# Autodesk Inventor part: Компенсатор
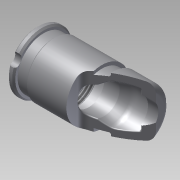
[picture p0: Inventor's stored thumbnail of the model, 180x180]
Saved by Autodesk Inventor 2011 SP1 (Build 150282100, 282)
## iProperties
Created: 2011-12
Part Number: Компенсатор
Document SubType Name: Modeling
Designer: EfimchenkoPA
Density: 1 g/cm^3
Author: EfimchenkoPA
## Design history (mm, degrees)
sketch "Эскиз1"
  geometry: L1 (0, 0)-(7.485, 0); L2 (0, 7.8)-(0, 9); L3 (0.5, 9.5)-(1.5, 9.5); L4 (2, 9)-(2, 8.25); L5 (2, 8.25)-(5, 8.25); L6 (5, 8.25)-(5.5, 8.75); L7 (5.5, 8.75)-(20.5, 8.75); L8 (20.5, 8.75)-(20.5, 7.75); L9 (20.5, 7.75)-(24.1, 7.75); L10 (24.1, 7.75)-(24.1, 8.75); L11 (24.1, 8.75)-(31.5, 8.75); L12 (33.5, 6.75)-(33.5, 5); L13 (33.5, 5)-(30.2, 5); L14 (30.2, 5)-(30.2, 6.5); L15 (30.2, 6.5)-(25.287, 6.5); L16 (23.596, 6.125)-(21.183, 5); L17 (21.183, 5)-(16.3, 5); L18 (16.3, 5)-(16.3, 7.05); L19 (16.3, 7.05)-(12.3, 7.05); L20 (12.3, 7.05)-(12.3, 7); L21 (12.3, 7)-(0.8, 7); L22 (0, 7.8)-(0.8, 7); L23 (0.5, 9.5)-(0, 9); L24 (1.5, 9.5)-(2, 9); A1 r 2 centre (31.5, 6.75) between (33.5, 6.75) and (31.5, 8.75); A2 r 4 centre (25.287, 2.5) between (25.287, 6.5) and (23.596, 6.125); 3 further points
  constraints: 48 end point, 14 parallel, 7 point on line, 4 perpendicular, 4 point on circle, 4 tangent, 2 centre point, 2 collinear, 1 horizontal
  dimensions: "d0" = 4 distance between parallel lines of L20 L18; "d1" = 7.05 distance between parallel lines of L19 L1; "d2" = 25 deg angle of L17 L16; "d3" = 5 distance between parallel lines of L17 L1; "d4" = 16.3 distance between parallel lines of L18 L2; "d5" = 7 distance between parallel lines of L1 L21; "d6" = 135 deg angle of L21 L22; "d7" = 0.8 horizontal distance of L2.start L21.end; "d8" = 8.25 distance between parallel lines of L1 L5; "d9" = 9.5 distance between parallel lines of L1 L3; "d10" = 2 distance between parallel lines of L2 L4; "d11" = 3 distance from line of L5.end L4; "d12" = 135 deg angle of L5 L6; "d13" = 8.75 distance between parallel lines of L7 L1; "d14" = 30.2 distance between parallel lines of L14 L2; "d15" = 5.8 distance from line of point (24.4, 6.5) L14; "d16" = 6.5 distance between parallel lines of L1 L15; "d17" = 2 radius of A1; "d18" = 33.5 distance between parallel lines of L12 L2; "d19" = 9.4 distance between parallel lines of L10 L12; "d20" = 3.6 distance between parallel lines of L8 L10; "d21" = 7.75 distance between parallel lines of L9 L1; "d22" = 4 radius of A2; "d23" = 0.5 distance of L3.start point (0, 9.5); "d24" = 0.5 distance of L2.end point (0, 9.5) (= d23); "d25" = 0.5 distance of L3.end point (2, 9.5) (= d23); "d26" = 0.5 distance of L4.start point (2, 9.5) (= d25)
revolve "Вращение1" sketch "Эскиз1" stored, may be unused: angle "d27" = 90 deg
sketch "Эскиз2"
  geometry: L1 (0, 9)-(0.5, 9.5) reference; L2 (0.5, 9.5)-(1.5, 9.5) reference; L3 (1.5, 9.5)-(2, 9) reference; L4 (2, 9)-(2, 8.25) reference; L5 (2, 8.25)-(5, 8.25) reference; L6 (5, 8.25)-(5.5, 8.75) reference; L7 (5.5, 8.75)-(20.5, 8.75) reference; L8 (20.5, 8.75)-(20.5, 7.75) reference; L9 (20.5, 7.75)-(24.1, 7.75) reference; L10 (24.1, 7.75)-(24.1, 8.75) reference; L11 (24.1, 8.75)-(31.5, 8.75) reference; L12 (33.5, 6.75)-(33.5, 5) reference; L13 (33.5, 5)-(30.2, 5) reference; L14 (30.2, 5)-(30.2, 6.5) reference; L15 (30.2, 6.5)-(25.287, 6.5) reference; L16 (23.596, 6.125)-(21.183, 5) reference; L17 (21.183, 5)-(16.3, 5) reference; L18 (16.3, 5)-(16.3, 7.05) reference; L19 (16.3, 7.05)-(12.3, 7.05) reference; L20 (12.3, 7.05)-(12.3, 7) reference; L21 (12.3, 7)-(0.8, 7) reference; L22 (0.8, 7)-(0, 7.8) reference; L23 (0, 7.8)-(0, 9) reference; L24 (0.5, -9.5)-(0, -9) reference; L25 (0, -9)-(0, -7.8) reference; L26 (0, -7.8)-(0.8, -7) reference; L27 (0.8, -7)-(12.3, -7) reference; L28 (12.3, -7)-(12.3, -7.05) reference; L29 (12.3, -7.05)-(16.3, -7.05) reference; L30 (16.3, -7.05)-(16.3, -5) reference; L31 (16.3, -5)-(21.183, -5) reference; L32 (21.183, -5)-(23.596, -6.125) reference; L33 (25.287, -6.5)-(30.2, -6.5) reference; L34 (30.2, -6.5)-(30.2, -5) reference; L35 (30.2, -5)-(33.5, -5) reference; L36 (33.5, -5)-(33.5, -6.75) reference; L37 (31.5, -8.75)-(24.1, -8.75) reference; L38 (24.1, -8.75)-(24.1, -7.75) reference; L39 (24.1, -7.75)-(20.5, -7.75) reference; L40 (20.5, -7.75)-(20.5, -8.75) reference; L41 (20.5, -8.75)-(5.5, -8.75) reference; L42 (5.5, -8.75)-(5, -8.25) reference; L43 (5, -8.25)-(2, -8.25) reference; L44 (2, -8.25)-(2, -9) reference; L45 (2, -9)-(1.5, -9.5) reference; L46 (1.5, -9.5)-(0.5, -9.5) reference; L47 (18, -18.426)-(18, -5.689); L48 (19.615, -3.028)-(44.535, 9.944); L49 (44.535, 9.944)-(44.535, -18.426); L50 (44.535, -18.426)-(18, -18.426); A1 r 2 centre (31.5, 6.75) between (33.5, 6.75) and (31.5, 8.75) reference; A2 r 4 centre (25.287, 2.5) between (25.287, 6.5) and (23.596, 6.125) reference; A3 r 4 centre (25.287, -2.5) between (23.596, -6.125) and (25.287, -6.5) reference; A4 r 2 centre (31.5, -6.75) between (31.5, -8.75) and (33.5, -6.75) reference; A5 r 3 centre (21, -5.689) between (19.615, -3.028) and (18, -5.689); 2 further points
  constraints: 8 end point, 2 perpendicular, 2 point on circle, 2 point on line, 2 tangent, 1 centre point, 1 parallel
  dimensions: "d28" = 4.2 vertical distance of point (33.5, 4.2) point (0, 0); "d29" = 18 distance between parallel lines of L25 L47; "d30" = 27.5 deg angle of L31 L48; "d31" = 3 radius of A5
extrude "Выдавливание1" cut sketch "Эскиз2" stored distance "d32" = 10; taper "d33" = 0 deg
fillet "Сопряжение3" dims "d36" = 0.3
fillet "Сопряжение1" dims "d34" = 0.3
sketch "Эскиз3" dims "d39" = 4
  geometry: L1 (0, 0)-(2.518, 0); L2 (0, 0)-(4.994, -9.009); C1 r 9 at (0, 0) reference; C2 r 7.8 at (0, 0) reference; 1 further point
  constraints: 4 end point, 1 horizontal, 1 point on line, 3 other
  dimensions: "d37" = 61 deg angle of L2 L1; "d38" = 8.3 distance of point (4.024, -7.259) C1.centre
extrude "Выдавливание2" cut sketch "Эскиз3" distance "d40" = 3; taper "d41" = 0 deg
fillet "Сопряжение4" dims "d47" = 0.5
sketch "Эскиз4"
  geometry: L1 (0, 9)-(0.5, 9.5) reference; L2 (0.5, 9.5)-(1.5, 9.5) reference; L3 (1.5, 9.5)-(2, 9) reference; L4 (2, 9)-(2, 8.25) reference; L5 (2, 8.25)-(5, 8.25) reference; L6 (5, 8.25)-(5.5, 8.75) reference; L7 (5.5, 8.75)-(20.5, 8.75) reference; L8 (20.5, 8.75)-(20.5, 7.75) reference; L9 (20.5, 7.75)-(23.6, 7.75) reference; L10 (24.1, 8.25)-(24.1, 8.75) reference; L11 (24.1, 8.75)-(31.5, 8.75) reference; L12 (33.5, 6.75)-(33.5, 5) reference; L13 (33.5, 5)-(30.2, 5) reference; L14 (30.2, 5)-(30.2, 6.2) reference; L15 (29.9, 6.5)-(25.287, 6.5) reference; L16 (23.596, 6.125)-(21.244, 5.028) reference; L17 (21.117, 5)-(16.3, 5) reference; L18 (16.3, 5)-(16.3, 7.05) reference; L19 (16.3, 7.05)-(12.3, 7.05) reference; L20 (12.3, 7.05)-(12.3, 7) reference; L21 (12.3, 7)-(0.8, 7) reference; L22 (0.8, 7)-(0, 7.8) reference; L23 (0, 7.8)-(0, 9) reference; L24 (0.5, -9.5)-(0, -9) reference; L25 (0, -9)-(0, -7.8) reference; L26 (0, -7.8)-(0.8, -7) reference; L27 (0.8, -7)-(12.3, -7) reference; L28 (12.3, -7)-(12.3, -7.05) reference; L29 (12.3, -7.05)-(16.3, -7.05) reference; L30 (16.3, -7.05)-(16.3, -5) reference; L31 (16.3, -5)-(17.723, -5) reference; L32 (18, -5.689)-(18, -8.75) reference; L33 (18, -8.75)-(5.5, -8.75) reference; L34 (5.5, -8.75)-(5, -8.25) reference; L35 (5, -8.25)-(2, -8.25) reference; L36 (2, -8.25)-(2, -9) reference; L37 (2, -9)-(1.5, -9.5) reference; L38 (1.5, -9.5)-(0.5, -9.5) reference; L39 (38.793, 16.5)-(38.793, 7.75); L40 (38.793, 7.75)-(23.359, 7.75); L41 (13.437, 16.5)-(38.793, 16.5); A1 r 2 centre (31.5, 6.75) between (33.5, 6.75) and (31.5, 8.75) reference; A2 r 0.3 centre (29.9, 6.2) between (30.2, 6.2) and (29.9, 6.5) reference; A3 r 4 centre (25.287, 2.5) between (25.287, 6.5) and (23.596, 6.125) reference; A4 r 0.3 centre (21.117, 5.3) between (21.117, 5) and (21.244, 5.028) reference; A5 r 3 centre (21, -5.689) between (18.021, -5.335) and (18, -5.689) reference; A6 r 10 centre (23.359, 17.75) between (13.437, 16.5) and (23.359, 7.75); A7 r 0.5 centre (23.6, 8.25) between (23.6, 7.75) and (24.1, 8.25) reference; 2 further points
  constraints: 6 end point, 3 point on circle, 2 perpendicular, 2 point on line, 1 centre point, 1 horizontal, 1 tangent, 1 other
  dimensions: "d42" = 7.75 distance from line of point (0, 0) L40; "d43" = 1.5 distance from line of point (19, 8.75) L8; "d44" = 10 radius of A6
extrude "Выдавливание3" cut sketch "Эскиз4" stored distance "d45" = 3; taper "d46" = 0 deg
feature "Резьба1" dims "d48" = 10, "d49" = 0
node "Твердое тело1"
node "Проецирование ребер1"
node "Проецирование ребер2"
